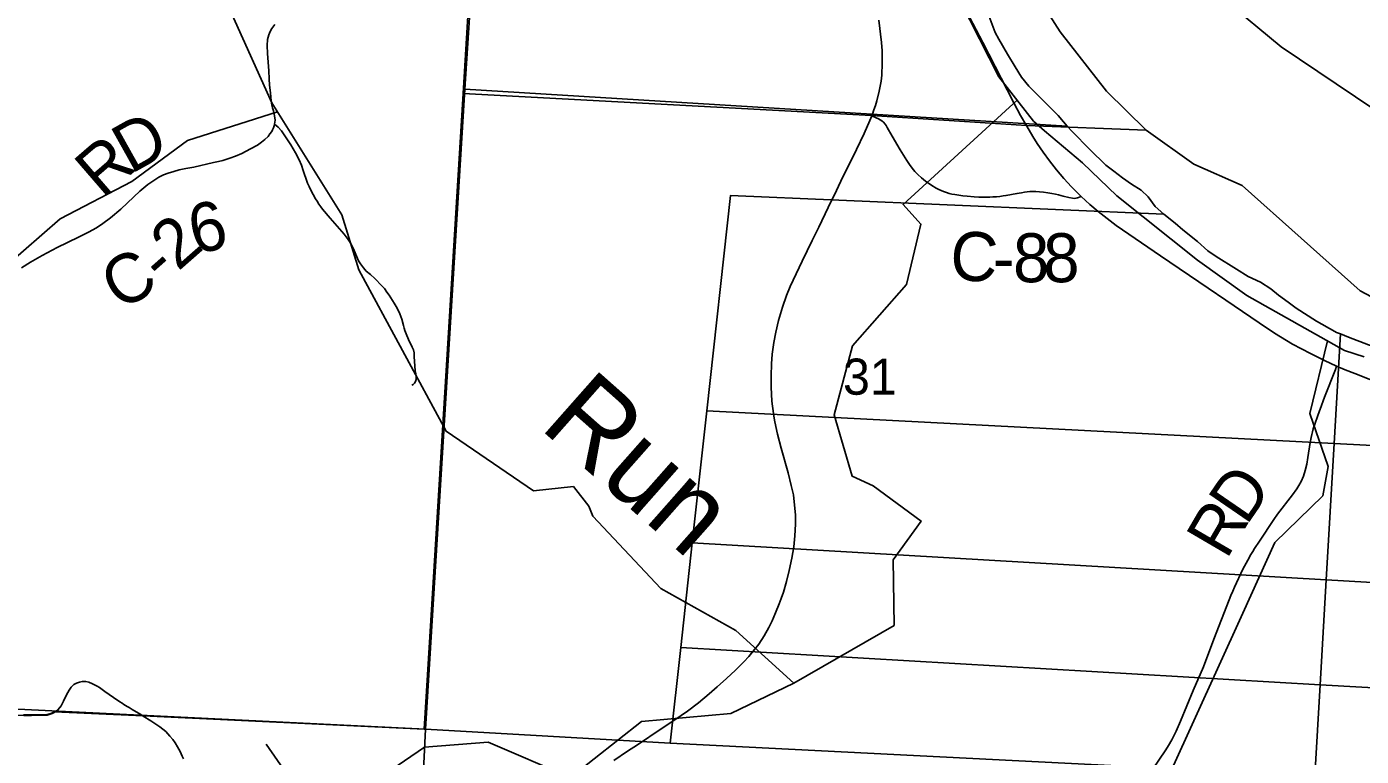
# Model space of a CAD drawing. Extents: x 21.4 to 65.3, y 4 to 26.
# Drawn here: x 25.873 to 27.421, y 20.4 to 21.246 of the extents above; entities that cross this region are included whole.
import ezdxf

# ---------------------------------------------------------------- set-up
doc = ezdxf.new("R2010")
doc.units = 0
for name, color, linetype in [('Default', 7, 'Continuous'), ('GM_X_County_Road', 7, 'Continuous'), ('GM_X_County_Road_Text', 7, 'Continuous'), ('GM_X_Major_River', 7, 'Continuous'), ('GM_X_Minor_River', 7, 'Continuous'), ('GM_X_Minor_River_Text', 7, 'Continuous'), ('GM_X_Section', 7, 'Continuous'), ('GM_X_Section_Text', 7, 'Continuous'), ('GM_X_State_Route', 7, 'Continuous'), ('GM_X_Township_Road', 7, 'Continuous'), ('SH_Cut_Line', 7, 'Continuous')]:
    doc.layers.add(name, color=color, linetype=linetype)

msp = doc.modelspace()

# ---------------------------------------------------------------- linework, layer by layer
at = {"layer": 'Default'}
for points in [[(25.869, 20.4484), (25.878, 20.4484), (25.89, 20.4485), (25.896, 20.4488), (25.9007, 20.45), (25.9039, 20.4514), (25.9047, 20.4519), (26.0076, 20.4475), (26.3338, 20.4317), (26.379, 21.1689), (26.3906, 21.3613), (26.4573, 22.45)], [(26.4573, 22.45), (26.3906, 21.3613), (26.379, 21.1689), (26.8527, 21.1433), (27.0325, 21.1315), (27.1713, 21.1261), (27.125, 21.1713), (27.0715, 21.2402), (26.9875, 21.3717), (26.9395, 21.4715), (26.8968, 21.6757), (26.8802, 21.8461), (26.8806, 21.8662), (26.8662, 22.382)], [(28.1702, 20.2638), (28.0527, 20.4505), (27.9586, 20.5583), (27.8546, 20.6506), (27.8422, 20.6714), (27.7163, 20.7618), (27.578, 20.8563), (27.4195, 20.94), (27.2824, 21.0623), (27.2266, 21.087), (27.1713, 21.1261), (27.0325, 21.1315), (26.8527, 21.1433), (26.379, 21.1689), (26.3338, 20.4317), (26.0076, 20.4475), (25.9047, 20.4519), (25.9039, 20.4514), (25.9007, 20.45), (25.896, 20.4488), (25.89, 20.4485), (25.878, 20.4484), (25.869, 20.4484)]]:
    msp.add_lwpolyline(points, dxfattribs=at)
at = {"layer": 'GM_X_County_Road'}
for points in [[(25.8666, 20.9666), (25.877, 20.9734), (25.8905, 20.981), (25.9081, 20.9902), (25.9327, 21.0021), (25.9444, 21.008), (25.9537, 21.0131), (25.961, 21.0179), (25.9698, 21.0248), (25.9817, 21.0348), (25.9967, 21.0488), (26.004, 21.0555), (26.013, 21.0632), (26.0199, 21.0681), (26.0258, 21.0717), (26.0311, 21.0744), (26.0367, 21.0765), (26.0432, 21.0785), (26.0496, 21.0801), (26.0573, 21.0817), (26.0666, 21.0835), (26.0892, 21.0886), (26.0952, 21.09), (26.1001, 21.0912), (26.1037, 21.0922), (26.1082, 21.0938), (26.1149, 21.0961), (26.1223, 21.0992), (26.1321, 21.1045), (26.1404, 21.109), (26.1451, 21.1122), (26.149, 21.1153), (26.1525, 21.1189), (26.1547, 21.122), (26.1568, 21.1249), (26.1577, 21.1266), (26.1589, 21.129), (26.1595, 21.1311), (26.1602, 21.1333), (26.1606, 21.1355), (26.1609, 21.138), (26.1606, 21.1404), (26.1602, 21.1424), (26.1596, 21.1451), (26.1587, 21.1485), (26.1577, 21.1522), (26.1574, 21.1536), (26.1569, 21.1553), (26.1566, 21.1575), (26.1563, 21.1599), (26.1556, 21.1653), (26.155, 21.1726), (26.1544, 21.1786), (26.154, 21.1856), (26.1533, 21.1951), (26.152, 21.2153), (26.1517, 21.2246), (26.1521, 21.2312), (26.1533, 21.2366), (26.1549, 21.2407), (26.1569, 21.2441), (26.1606, 21.2487)], [(26.8529, 21.1428), (26.8579, 21.1406), (26.8607, 21.1393), (26.8626, 21.1383), (26.8647, 21.1369), (26.8665, 21.1354), (26.8683, 21.1334), (26.8696, 21.1315), (26.8707, 21.1295), (26.8767, 21.1192), (26.8858, 21.1034), (26.8935, 21.0912), (26.8967, 21.0865), (26.8998, 21.0822), (26.903, 21.0783), (26.9064, 21.0747), (26.9105, 21.0709), (26.9154, 21.067), (26.9225, 21.062), (26.9276, 21.059), (26.9307, 21.0574), (26.9332, 21.0563), (26.9362, 21.0551), (26.9397, 21.0539), (26.9427, 21.0529), (26.9459, 21.0522), (26.9494, 21.0515), (26.954, 21.0508), (26.9586, 21.0502), (26.9637, 21.0496), (26.9715, 21.049), (26.9771, 21.0487), (26.9819, 21.0485), (26.9856, 21.0485), (26.9897, 21.0486), (26.9935, 21.0488), (26.9974, 21.0491), (27.0015, 21.0495), (27.0053, 21.05), (27.0087, 21.0506), (27.0212, 21.0528), (27.0267, 21.0538), (27.03, 21.0543), (27.0331, 21.0547), (27.0361, 21.055), (27.0394, 21.055), (27.0431, 21.055), (27.0474, 21.0548), (27.0522, 21.0542), (27.0573, 21.0535), (27.0618, 21.0527), (27.0659, 21.0519), (27.0694, 21.0512), (27.0749, 21.0499), (27.0815, 21.0483), (27.0856, 21.0475), (27.0875, 21.0472), (27.0896, 21.0473), (27.0917, 21.0479), (27.0956, 21.0494)], [(27.3732, 20.8029), (27.3782, 20.8166), (27.3907, 20.849), (27.3921, 20.8527)], [(27.1785, 20.3851), (27.1939, 20.4078), (27.1971, 20.413), (27.2008, 20.4194), (27.2036, 20.4249), (27.2058, 20.4294), (27.211, 20.4413), (27.2259, 20.4768), (27.2376, 20.504), (27.2497, 20.5361), (27.2673, 20.5817), (27.2695, 20.587), (27.2716, 20.592), (27.2736, 20.5965), (27.2835, 20.6174), (27.289, 20.6278), (27.2927, 20.6343), (27.2949, 20.638), (27.2969, 20.6412), (27.3026, 20.65), (27.3193, 20.675), (27.3236, 20.681), (27.3409, 20.7035), (27.3459, 20.7106), (27.3482, 20.7143), (27.3509, 20.7191), (27.3536, 20.7253), (27.3557, 20.7317), (27.3575, 20.7389), (27.3588, 20.7468), (27.3615, 20.7641), (27.3625, 20.7699), (27.3632, 20.7733), (27.364, 20.7767), (27.3651, 20.7799), (27.3724, 20.8009), (27.3732, 20.8029)], [(26.0071, 20.4474), (26.005, 20.4488), (25.9948, 20.4547), (25.9914, 20.4569), (25.989, 20.4583), (25.9854, 20.4603), (25.9832, 20.4619), (25.9808, 20.4636), (25.9732, 20.4686), (25.9634, 20.4757), (25.9585, 20.479), (25.957, 20.48), (25.9543, 20.4817), (25.9488, 20.4846), (25.9447, 20.4862), (25.941, 20.487), (25.9371, 20.4871), (25.9339, 20.4865), (25.9304, 20.4853), (25.9274, 20.4836), (25.9243, 20.4806), (25.9218, 20.4771), (25.9187, 20.4715), (25.9153, 20.4645), (25.9126, 20.4591), (25.9092, 20.4546), (25.9065, 20.4524), (25.9049, 20.4514), (25.9041, 20.4509)], [(25.9041, 20.4509), (25.9009, 20.4495), (25.8962, 20.4482), (25.8902, 20.448), (25.8782, 20.4479), (25.8693, 20.4478), (25.8554, 20.4483), (25.8461, 20.4487), (25.8393, 20.4494), (25.8344, 20.45), (25.8312, 20.4504), (25.8189, 20.4517), (25.8092, 20.4521), (25.8004, 20.452), (25.7911, 20.4514), (25.7899, 20.4513)], [(26.0544, 20.3973), (26.053, 20.4005), (26.0506, 20.4061), (26.0477, 20.4113), (26.0448, 20.416), (26.0421, 20.4199), (26.0388, 20.4239), (26.0338, 20.4291), (26.0271, 20.4346), (26.0166, 20.4415), (26.0078, 20.447), (26.0071, 20.4474)]]:
    msp.add_lwpolyline(points, dxfattribs=at)
at = {"layer": 'GM_X_Major_River'}
for points in [[(26.828, 22.3063), (26.8227, 22.1096), (26.8201, 22.0067), (26.8276, 21.9186), (26.8322, 21.8203), (26.8443, 21.7103), (26.8561, 21.5999), (26.8712, 21.5206), (26.8785, 21.4842), (26.9, 21.4087), (26.9282, 21.3405), (26.9553, 21.2761), (27.0003, 21.1882), (27.0406, 21.1367), (27.0531, 21.1254), (27.0975, 21.0883), (27.1373, 21.0502), (27.2306, 20.9757), (27.2878, 20.9346), (27.4011, 20.8709), (27.4242, 20.8634)], [(27.478, 21.1221), (27.3279, 21.2229), (27.2623, 21.2769), (27.2004, 21.3526), (27.1817, 21.3829), (27.1596, 21.4257), (27.1306, 21.5038), (27.1149, 21.5592), (27.0846, 21.6634), (27.0744, 21.7378), (27.0729, 21.7511), (27.0604, 21.8516), (27.05, 21.9879), (27.0452, 22.0577), (27.0481, 22.0824)]]:
    msp.add_lwpolyline(points, dxfattribs=at)
at = {"layer": 'GM_X_Minor_River'}
for points in [[(27.0214, 21.1612), (26.8893, 21.04), (26.9098, 21.0174), (26.8932, 20.9474), (26.8304, 20.8763), (26.8094, 20.7964), (26.8301, 20.7252), (26.8545, 20.714), (26.9101, 20.6731), (26.8777, 20.6281), (26.8787, 20.5522), (26.7623, 20.4851), (26.695, 20.5464), (26.6082, 20.5949), (26.5293, 20.6789), (26.5246, 20.6902), (26.5068, 20.7132), (26.4606, 20.7082), (26.359, 20.7772), (26.2579, 20.9645), (26.2381, 21.0281), (26.157, 21.158), (26.1109, 21.2601)], [(26.1634, 21.1477), (26.0593, 21.1142), (25.9946, 21.0666), (25.9113, 21.0233), (25.8261, 20.9493), (25.6456, 20.8706), (25.5194, 20.8558), (25.4603, 20.877), (25.4397, 20.9106), (25.3659, 20.9266), (25.2916, 20.8861), (25.1879, 20.8054), (25.1159, 20.7919), (25.027, 20.889), (24.95, 20.9096), (24.9385, 20.919), (24.8667, 20.9548)], [(27.3815, 20.8819), (27.361, 20.7979), (27.3823, 20.7362), (27.3763, 20.7024), (27.3204, 20.6483), (27.2832, 20.5664), (27.199, 20.3812), (27.1602, 20.2468), (27.1225, 20.1956), (27.0381, 20.1235), (27.0025, 20.0276), (26.8937, 19.871), (26.8794, 19.8549)], [(26.7623, 20.4851), (26.6894, 20.4499), (26.5859, 20.4406), (26.5033, 20.3757), (26.4078, 20.417), (26.3342, 20.411), (26.2255, 20.3368), (26.1899, 20.3578), (26.1505, 20.4143)]]:
    msp.add_lwpolyline(points, dxfattribs=at)
at = {"layer": 'GM_X_Section'}
for points in [[(26.3977, 21.4352), (26.3809, 21.1738), (26.3352, 20.4317), (25.2871, 20.4832), (25.275, 20.4836), (25.3384, 21.4821)], [(26.9221, 21.4076), (26.9241, 21.3999), (26.9314, 21.3806), (26.9382, 21.3636), (26.944, 21.3511), (26.9478, 21.3428), (26.9604, 21.3178), (26.968, 21.3004), (26.9734, 21.2909), (26.9795, 21.2773), (26.9856, 21.2645), (26.989, 21.258), (26.9959, 21.2395), (27.0001, 21.2319), (27.0104, 21.2145), (27.0191, 21.1998), (27.0267, 21.1877), (27.0351, 21.1771), (27.0481, 21.1643), (27.069, 21.1431), (27.0754, 21.136), (27.0797, 21.131), (26.3809, 21.1738), (26.3977, 21.4352)], [(27.0797, 21.131), (27.0853, 21.1246), (27.1058, 21.1039), (27.1245, 21.0857), (27.1336, 21.0789), (27.1439, 21.071), (27.1541, 21.0635), (27.1655, 21.0567), (27.1735, 21.0488), (27.1815, 21.0378), (27.1917, 21.029), (26.689, 21.0504), (26.6615, 20.8008), (26.6446, 20.6478), (26.6312, 20.5264), (26.6191, 20.4157), (26.3352, 20.4317), (26.3809, 21.1738)], [(27.1917, 21.029), (27.2047, 21.0186), (27.2138, 21.0106), (27.2309, 20.9971), (27.2427, 20.9865), (27.2522, 20.9797), (27.2761, 20.965), (27.2894, 20.9567), (27.3038, 20.95), (27.3159, 20.9424), (27.3247, 20.9349), (27.3361, 20.927), (27.3452, 20.9198), (27.3687, 20.9047), (27.39, 20.8927), (27.392, 20.8919), (27.3965, 20.8901), (27.3892, 20.763), (26.6615, 20.8008), (26.689, 21.0504)], [(27.3892, 20.763), (27.3965, 20.8901), (27.4059, 20.8863), (27.4291, 20.8776), (27.4439, 20.8724), (27.4643, 20.8687), (27.4799, 20.8649), (27.4962, 20.8597), (27.5148, 20.8499), (27.5349, 20.839), (27.5619, 20.8239), (27.5884, 20.81), (27.6032, 20.8021), (27.6192, 20.7915), (27.6503, 20.7746), (27.6655, 20.7675), (27.6742, 20.7614), (27.6868, 20.7524), (27.6933, 20.7471)], [(26.6615, 20.8008), (27.3892, 20.763), (27.3801, 20.6051), (26.6446, 20.6478)], [(27.3892, 20.763), (27.6933, 20.7471), (27.705, 20.7377), (27.7259, 20.723), (27.7456, 20.7098), (27.7631, 20.6977), (27.7848, 20.6803), (27.8045, 20.6649), (27.8178, 20.6539), (27.8311, 20.6419), (27.8498, 20.6234), (27.8615, 20.6139), (27.8756, 20.6037), (27.8889, 20.5924), (27.9007, 20.5815), (27.907, 20.5744), (27.3801, 20.6051)], [(27.3801, 20.6051), (27.3731, 20.4834), (26.6312, 20.5264), (26.6446, 20.6478)], [(27.907, 20.5744), (27.9163, 20.5641), (27.9311, 20.5501), (27.944, 20.5384), (27.9581, 20.5226), (27.9771, 20.501), (27.9866, 20.4908), (27.9965, 20.4784), (28.0037, 20.4693), (28.0136, 20.4587), (28.0222, 20.4469), (27.3731, 20.4834), (27.3801, 20.6051)], [(26.6312, 20.5264), (27.3731, 20.4834), (27.367, 20.3777), (26.6191, 20.4157)], [(25.2871, 20.4832), (26.3352, 20.4317), (26.3235, 20.1926), (26.3057, 19.938), (26.289, 19.6776), (26.2711, 19.4096), (26.2708, 19.4063), (25.208, 19.459)], [(27.3731, 20.4834), (28.0222, 20.4469), (28.0334, 20.4311), (28.0422, 20.4171), (28.0647, 20.3839), (28.073, 20.3722), (28.0829, 20.3589), (28.0906, 20.3484), (28.1023, 20.3397), (27.6101, 20.3651), (27.367, 20.3777)], [(26.3352, 20.4317), (26.6191, 20.4157), (27.367, 20.3777), (27.3527, 20.1302), (26.3235, 20.1926)]]:
    msp.add_lwpolyline(points, close=True, dxfattribs=at)
at = {"layer": 'GM_X_State_Route'}
msp.add_line((26.8529, 21.1428), (26.8536, 21.1448), dxfattribs=at)
for points in [[(27.0327, 21.131), (27.0255, 21.1434), (27.0182, 21.1571), (27.0099, 21.173), (26.9818, 21.2278), (26.9582, 21.2729), (26.9412, 21.3054), (26.929, 21.3292), (26.9187, 21.3505), (26.9113, 21.3669), (26.9051, 21.3819), (26.9, 21.3953), (26.8945, 21.4112), (26.8893, 21.4278), (26.8879, 21.433), (26.8826, 21.4517), (26.8796, 21.4628)], [(26.8536, 21.1448), (26.8553, 21.1497), (26.8571, 21.155), (26.8587, 21.1601), (26.8615, 21.1715), (26.8636, 21.183), (26.8644, 21.19), (26.8651, 21.204), (26.8649, 21.2182), (26.864, 21.2277), (26.861, 21.2536)], [(26.7393, 20.7949), (26.7388, 20.7978), (26.7371, 20.8122), (26.7363, 20.8285), (26.736, 20.8413), (26.7365, 20.8552), (26.7374, 20.8667), (26.7393, 20.8803), (26.7414, 20.892), (26.7447, 20.9055), (26.7493, 20.9211), (26.754, 20.9347), (26.7583, 20.9451), (26.7723, 20.9745), (26.7838, 20.9982), (26.7914, 21.0139), (26.8024, 21.0365), (26.8119, 21.0562), (26.8195, 21.072), (26.8243, 21.0818), (26.835, 21.1038), (26.844, 21.1224), (26.8507, 21.1373), (26.8529, 21.1428)], [(27.3921, 20.8527), (27.3779, 20.8592), (27.3617, 20.8673), (27.341, 20.8783), (27.3199, 20.891), (27.3023, 20.903), (27.2637, 20.9291), (27.2433, 20.9431), (27.1879, 20.9804), (27.1363, 21.0159), (27.1258, 21.0237), (27.1155, 21.032), (27.106, 21.0402), (27.0956, 21.0494), (27.0846, 21.0606), (27.0756, 21.0702), (27.0672, 21.0804), (27.0591, 21.0909), (27.0517, 21.1009), (27.0449, 21.1107), (27.0396, 21.1191), (27.0327, 21.131)], [(27.445, 20.8327), (27.4412, 20.8339), (27.43, 20.8377), (27.4131, 20.8441), (27.4021, 20.8484), (27.3921, 20.8527)], [(26.5537, 20.3954), (26.5694, 20.4062), (26.581, 20.4139), (26.6085, 20.4323), (26.6243, 20.4426), (26.6392, 20.4529), (26.652, 20.4624), (26.6643, 20.473), (26.6736, 20.4808), (26.6844, 20.4908), (26.6948, 20.5004), (26.7043, 20.51), (26.7103, 20.5161), (26.7169, 20.5243), (26.7218, 20.5306), (26.7281, 20.5401), (26.7336, 20.5496), (26.7373, 20.5574), (26.7412, 20.5667), (26.7455, 20.5772), (26.7477, 20.5835), (26.7503, 20.5906), (26.754, 20.6029), (26.7572, 20.6159), (26.7602, 20.6302), (26.7623, 20.6433), (26.7637, 20.6561), (26.7645, 20.6696), (26.7643, 20.6804), (26.7634, 20.6917), (26.7619, 20.7035), (26.7595, 20.7143), (26.7558, 20.729), (26.7478, 20.7577), (26.7434, 20.7739), (26.7403, 20.7881), (26.7393, 20.7949)]]:
    msp.add_lwpolyline(points, dxfattribs=at)
at = {"layer": 'GM_X_Township_Road'}
msp.add_lwpolyline([(26.3193, 20.8308), (26.321, 20.8316), (26.3225, 20.8328), (26.3237, 20.8349), (26.3243, 20.8373), (26.3243, 20.8398), (26.3238, 20.8439), (26.3234, 20.8471), (26.3228, 20.8532), (26.3226, 20.8581), (26.3222, 20.864), (26.3219, 20.8683), (26.3211, 20.8718), (26.3196, 20.8747), (26.3156, 20.8835), (26.3129, 20.8901), (26.3112, 20.8941), (26.3103, 20.8968), (26.3095, 20.9), (26.3078, 20.9073), (26.3056, 20.9134), (26.3022, 20.92), (26.2989, 20.9257), (26.293, 20.9349), (26.2905, 20.9385), (26.2876, 20.9426), (26.2849, 20.9454), (26.2824, 20.948), (26.2787, 20.952), (26.2764, 20.9545), (26.2712, 20.959), (26.2665, 20.9629), (26.2631, 20.9665), (26.2596, 20.9713), (26.2573, 20.9749), (26.2515, 20.9888), (26.2489, 20.9941), (26.2454, 20.9997), (26.2409, 21.0057), (26.2247, 21.0241), (26.2159, 21.0345), (26.2139, 21.0373), (26.2116, 21.0405), (26.2095, 21.0439), (26.2077, 21.0468), (26.2023, 21.0566), (26.2003, 21.0609), (26.1984, 21.065), (26.1963, 21.0706), (26.1947, 21.0749), (26.1931, 21.0796), (26.1912, 21.0856), (26.1886, 21.092), (26.1845, 21.0999), (26.1788, 21.1093), (26.168, 21.1254), (26.1642, 21.1296), (26.1621, 21.1318), (26.1602, 21.1333)], dxfattribs=at)
at = {"layer": 'SH_Cut_Line'}
msp.add_lwpolyline([(28.1702, 20.2638), (28.0527, 20.4505), (27.9586, 20.5583), (27.8546, 20.6506), (27.8422, 20.6714), (27.7163, 20.7618), (27.578, 20.8563), (27.4195, 20.94), (27.2824, 21.0623), (27.2266, 21.087), (27.1713, 21.1261), (27.125, 21.1713), (27.0715, 21.2402), (26.9875, 21.3717), (26.9395, 21.4715), (26.8968, 21.6757), (26.8802, 21.8461), (26.8806, 21.8662), (26.8662, 22.382)], dxfattribs=at)

# ---------------------------------------------------------------- texts
at = {"layer": 'GM_X_County_Road_Text'}
for s, rotation, p in [('D', 29.228, (25.9933, 21.0749)), ('R', 40.8386, (25.9605, 21.0461)), ('6', 13.3433, (26.068, 20.9818)), ('2', 41.2716, (26.0481, 20.962)), ('C', 355.9044, (26.9423, 20.9535)), ('8', 359.9506, (27.0167, 20.95)), ('8', 359.9992, (27.0517, 20.95)), ('C', 30.7877, (25.9812, 20.9159)), ('-', 41.4489, (26.0306, 20.9466)), ('-', 0.0272, (26.9933, 20.95)), ('D', 55.5613, (27.2874, 20.6669)), ('R', 59.6882, (27.2644, 20.6275))]:
    msp.add_text(s, height=0.0568, rotation=rotation, dxfattribs=at).set_placement(p)
at = {"layer": 'GM_X_Minor_River_Text'}
msp.add_text('Run', height=0.0947, rotation=318.511, dxfattribs=at).set_placement((26.466, 20.7816))
at = {"layer": 'GM_X_Section_Text'}
msp.add_text('31', height=0.04186, rotation=0, dxfattribs=at).set_placement((26.8195, 20.8196))

doc.saveas('drawing.dxf')
